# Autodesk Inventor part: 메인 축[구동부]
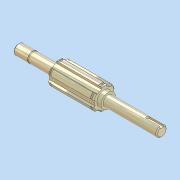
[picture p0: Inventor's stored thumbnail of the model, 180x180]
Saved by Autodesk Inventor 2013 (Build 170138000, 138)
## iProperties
Company: 한국ATC센터
Created: 2012-05
Part Number: 메인 축[구동부]
Document SubType Name: 모델링
Designer: KYOUNG IL JANG
Mass: 168.566 g
Surface Area: 72.5104 cm^2
Volume: 21.4461 cm^3
Density: 7.86 g/cm^3
Material: 강, 연강
변환 표준: STEP AP214IS
파일 이름: C:\Users\SeoGD\Desktop\?쒗뿕\硫붿씤 異?.stp
전처리기: Build: 253, Release: 2010 SP1 - Date: Wed 07/29/2009
전송 단위: 밀리미터
불확실성: 0.01
Author: KYOUNG IL JANG
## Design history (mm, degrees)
sketch "스케치1"
  geometry: L1 (-69.5, 0)-(69.5, 0); L2 (69.5, 0)-(69.5, 5); L3 (69.5, 5)-(55.5, 5); L4 (55.5, 5)-(55.5, 4.8); L5 (55.5, 4.8)-(54.35, 4.8); L6 (54.35, 4.8)-(54.35, 5); L7 (54.35, 5)-(30.5, 5); L8 (30.5, 5)-(30.5, 9); L9 (30.5, 9)-(-13.5, 9); L10 (-13.5, 9)-(-13.5, 7); L11 (-13.5, 7)-(-17.5, 7); L12 (-17.5, 7)-(-17.5, 5); L13 (-17.5, 5)-(-69.5, 5); L14 (-69.5, 5)-(-69.5, 0); 2 further points
  constraints: 28 end point, 9 parallel, 4 collinear, 2 perpendicular, 1 coincident, 1 horizontal, 1 midpoint
  dimensions: "d2" = 1.15 distance between parallel lines of L6 L4; "d3" = 10 diameter of L3 L1; "d4" = 9.6 diameter of L5 L1; "d6" = 44 distance between parallel lines of L10 L8; "d7" = 4 distance between parallel lines of L12 L10; "d8" = 14 diameter of L11 L1; "d9" = 18 diameter of L9 L1; "d33" = 52 distance from line of L12.end L14; "d37" = 39 distance between parallel lines of L8 L2; "d38" = 14 distance between parallel lines of L2 L4
revolve "회전1" sketch "스케치1" stored, may be unused: angle "d10" = 90 deg
sketch "스케치2"
  geometry: L1 (2.5, 10.712)-(2.5, 8.646); L2 (-2.5, 10.712)-(-2.5, 8.646); A1 r 9 centre (0, 0) between (2.5, 8.646) and (-2.5, 8.646) reference; A2 r 11 centre (0, 0) between (2.5, 10.712) and (-2.5, 10.712); 1 further point
  constraints: 4 end point, 4 point on circle, 2 parallel, 1 centre point, 1 coincident, 1 vertical
  dimensions: "d11" = 22 diameter of A2; "d12" = 5 distance between parallel lines of L1 L2
extrude "돌출1" join sketch "스케치2" stored distance "d13" = 10; taper "d14" = 0 deg
chamfer "모따기1" distance "d15" = 1; stored, may be unused: second distance "d16" = 2, angle "d17" = 45 deg
node "작업 평면1"
node "작업 평면2"
sketch "스케치3"
  geometry: L1 (2.5, 10.712)-(2.5, 10.198); L2 (-2.5, 10.712)-(-2.5, 10.198); A1 r 11 centre (0, 0) between (2.5, 10.712) and (-2.5, 10.712) reference; A2 r 10.5 centre (0, 0) between (2.5, 10.198) and (-2.5, 10.198); 1 further point
  constraints: 4 end point, 2 point on circle, 1 centre point, 1 coincident, 1 parallel, 1 vertical
  dimensions: "d19" = 21 diameter of A2
extrude "돌출2" cut sketch "스케치3" distance "d20" = 1.35; taper "d21" = 0 deg
node "작업 평면3"
sketch "스케치4"
  geometry: L1 (-26, -5)-(-26, 5) reference; L2 (-26, 1.5)-(-12.5, 1.5); L3 (-12.5, -1.5)-(-26, -1.5); A1 r 1.5 centre (-12.5, 0) between (-12.5, -1.5) and (-12.5, 1.5); 2 further points
  constraints: 4 end point, 2 perpendicular, 2 point on circle, 2 point on line, 2 tangent, 1 centre point, 1 horizontal alignment, 1 midpoint
  dimensions: "d25" = 3 distance between parallel lines of L3 L2; "d26" = 15 dimension on A1 L1
extrude "돌출3" cut sketch "스케치4" distance "d27" = 1.8; taper "d28" = 0 deg
chamfer "모따기2" distance "d29" = 1; stored, may be unused: second distance "d30" = 2, angle "d31" = 45 deg
node "솔리드1"
node "솔리드 본체"
node "곡면 본체"
mirror "대칭1"
pattern_circular "원형 패턴1" dims "d23" = 360 deg
node "솔리드2"
other parameters: "d18" = -1.65
